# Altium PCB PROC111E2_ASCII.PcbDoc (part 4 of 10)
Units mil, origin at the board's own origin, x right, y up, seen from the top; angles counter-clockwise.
Board outline 7700 x 2300 mil, 6 copper layers (Top Layer, GND 1, SIG 1, SIG 2, GND 2, Bottom Layer), stack 78.711 mil thick; 767 components, 596 nets, 2755 pads, 1578 vias.
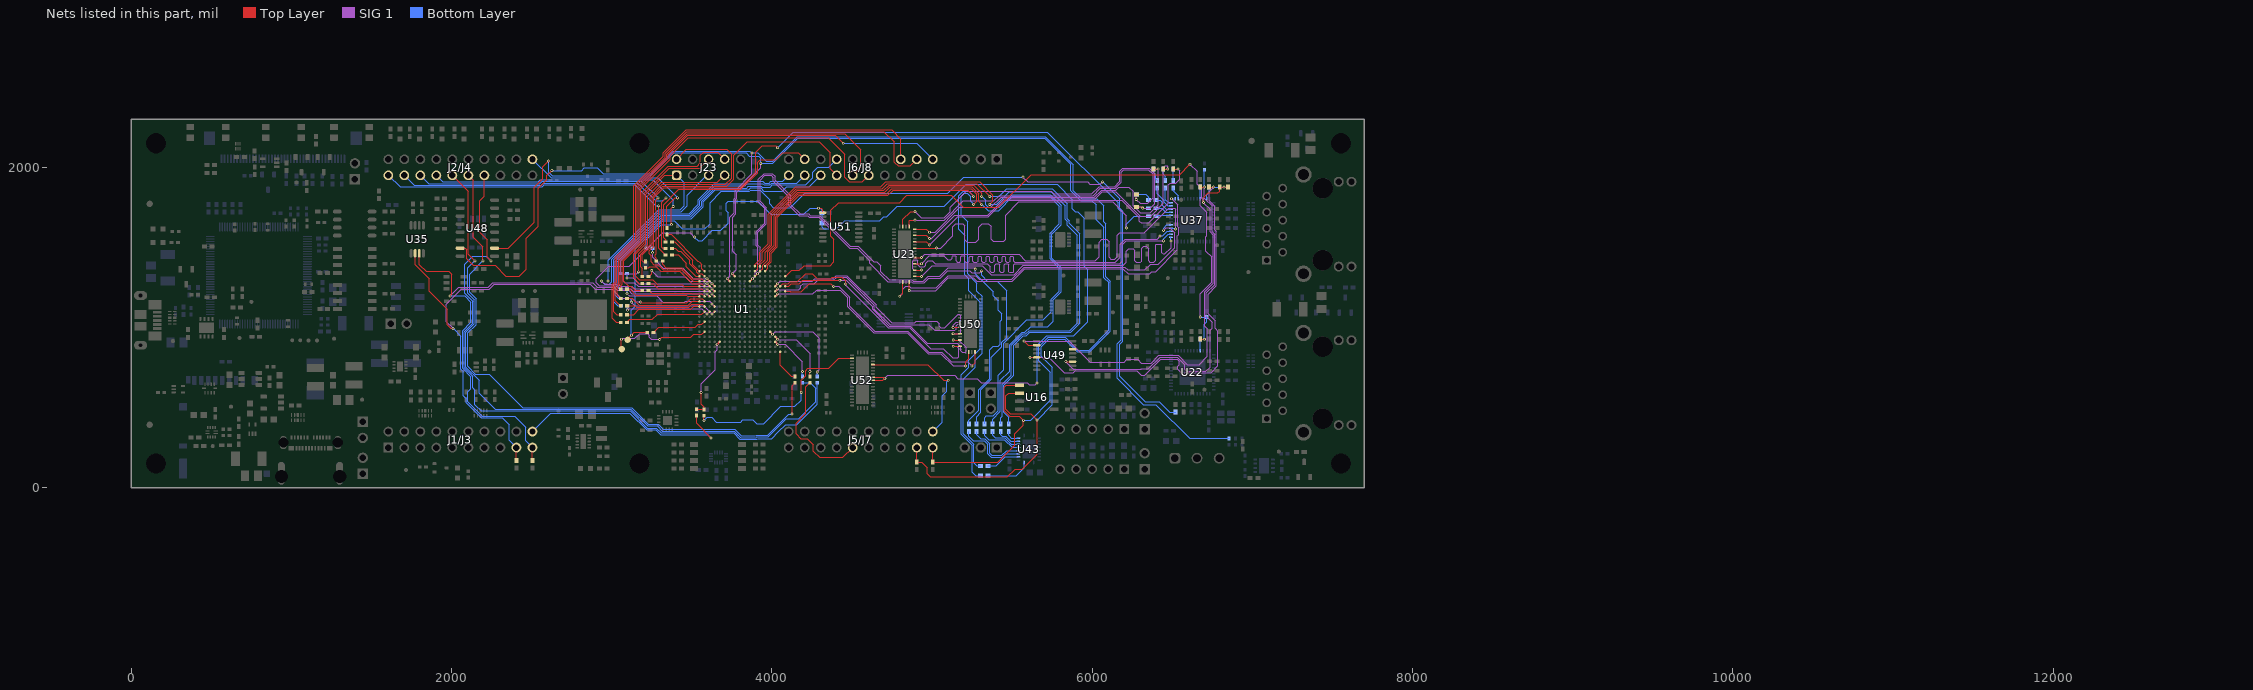
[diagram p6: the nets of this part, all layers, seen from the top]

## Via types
v1: diameter 18, hole 8, Top Layer to Bottom Layer, tented both sides, 1474 vias
v2: diameter 19.68, hole 7.87, Top Layer to Bottom Layer, tented both sides, 104 vias

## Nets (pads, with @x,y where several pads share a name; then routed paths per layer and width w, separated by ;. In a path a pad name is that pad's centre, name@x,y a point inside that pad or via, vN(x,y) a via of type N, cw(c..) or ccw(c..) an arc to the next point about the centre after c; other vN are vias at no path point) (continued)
AM263_BP_MUX_SEL_GPIO63: R298.2 R300.2 U1.G4 U51.1 U52.9 U52.10 | length 7040.3
  Top Layer w5.3: v1(4291.03,1744.24) 4306.84,1744.24 4317.8,1733.28 U51.1@4317.8,1717.48 ; U52.9@4629.96,670 4693.01,670 v1(4705,681.99) 4697.31,689.68 U52.10@4629.96,689.68
  Top Layer w10: v1(3625.87,1209.57) U1.G4@3641.62,1193.82
  SIG 1 w4: 3518.68,1226.06 3609.38,1226.06 v1(3625.87,1209.57)
  SIG 1 w4.75: v1(3515.64,1564.46) 3488.69,1591.41 3317.97,1591.41 3109.37,1382.8 2979.62,1382.8 2902.31,1305.49 2902.31,1278.83 2921.14,1260 3024.5,1260 3042.5,1242 3116.39,1242 3132.32,1226.06 3518.68,1226.06
  SIG 1 w5.3: v1(4705,681.99) 4723.17,700.16 5141.38,700.16 5161.5,680.04 5281.04,680.04 5305.58,655.5 5592.71,655.5 5605.21,643 5644.31,643 v1(5654.39,653.09)
  Bottom Layer w5.3: v1(3515.64,1564.46) 3538.74,1541.35 3563.03,1541.35 3627.8,1606.12 3680.51,1606.12 3726.52,1652.14 3726.52,1715.86 3713.62,1728.77 3713.62,1775.16 3725.58,1787.12 3911.05,1787.12 3991.69,1706.48 4199.68,1706.48 4237.44,1744.24 v1(4291.03,1744.24) 4301.08,1744.24 4312.89,1732.43 R298.2@4312.89,1715.49 R300.2@4312.89,1652.52 4312.89,1626.91 4323,1616.79 4405.75,1616.79 4453.96,1665 4672.04,1665 4697.54,1690.5 4717.5,1690.5 4783.54,1756.54 5075.54,1756.54 5212,1893 5782.5,1893 5876.5,1799 5876.5,1741.5 5894,1724 5908.74,1724 5951,1681.74 5951,1383.57 5972.85,1361.72 5972.85,1035.35 5885.7,948.2 5714.61,948.2 5655,888.59 5655,653.69 v1(5654.39,653.09)
AM263_CAN_STB_GPIO51: R248.2 U1.D1 | length 6072.1
  Top Layer w4: 3515.64,1288.31 U1.D1@3547.13,1288.31
  Top Layer w5.3: 3515.64,1288.31 3507.89,1288.31 3435.14,1361.06 3322.44,1361.06 3291,1392.5 3263,1392.5 3246.28,1409.22 3246.28,1447.41 3234.85,1458.85 3234.85,1478.14 3261.6,1504.89 3261.6,1810.22 3323.68,1872.3 3801.74,1872.3 3899.52,1970.08 3899.52,2094.24 3940.28,2135 4022.68,2135 v1(4035.32,2122.36)
  Bottom Layer w5.3: v1(4035.32,2122.36) 4132.97,2220 5720,2220 6161.25,1778.75 6161.25,1740.07 6179.88,1721.45 6179.88,922.38 6155,897.5 6155,683.66 6320,518.66 6397.07,518.66 6608.49,307.24 R248.2@6855,307.24
AM263_CLKOUT0: R4.2 R118.1 TP1.1 | length 5760.5
  Top Layer w5.3: TP1.1@3098.87,922.75 3098.87,928.07 v1(3122.32,951.52) 3139.85,969.06 R4.2@3221.22,969.06
  SIG 1 w4.75: v1(5567.49,1938.61) 5596.85,1909.25 5970.75,1909.25 5984.25,1895.75 6051.33,1895.75 v1(6065,1909.42)
  Bottom Layer w5.3: v1(3122.32,951.52) 3122.32,1108.82 3144.52,1131.02 3144.52,1491.6 3317.93,1665 3389.12,1665 3439.12,1615 3580,1615 3613.9,1648.9 3613.9,1778.89 3684.53,1849.52 3858.86,1849.52 3867.31,1857.97 3925.21,1857.97 3985,1798.18 3985,1773.13 4009.25,1748.88 4114.83,1748.88 4204.88,1838.92 5097.92,1838.92 5197.61,1938.61 v1(5567.49,1938.61) ; v1(6065,1909.42) 6171.85,1802.57 6171.85,1744.46 6190.48,1725.84 6190.48,912.98 6171.85,894.35 6171.85,695.04 6330,536.89 6417.03,536.89 6482.54,471.38 R118.1@6520,471.38
AM263_CLKOUT0_R: R4.1 U1.M2 | length 345.9
  Top Layer w4: 3539.45,1020.59 3562.88,1020.59 U1.M2@3578.63,1036.34
  Top Layer w5.3: R4.1@3260.59,969.06 3293.06,1001.54 3520.39,1001.54 3539.45,1020.59
AM263_DAC_OUT1: J1/J3.30 R45.1 | length 1403.7
  Top Layer w5.3: R45.1@3528.72,450.24 3528.72,400.34 v1(3618.83,310.23)
  Bottom Layer w5.3: J1/J3.30@2504.17,350 2619.17,465 3112.73,465 3216.45,361.28 3273.73,361.28 3304.51,330.5 3598.56,330.5 v1(3618.83,310.23)
AM263_DAC_OUT2: R3.1 U52.23 | length 1253.4
  Top Layer w5.3: v1(3575.19,418.7) R3.1@3575.19,448.84 ; v1(4182.78,594.53) 4181.82,595.49 4181.82,670.64 4209.52,698.35 4209.52,729.88 4223.55,743.91 4353.02,743.91 4416.91,807.8 U52.23@4500.04,807.8
  Bottom Layer w5.3: v1(3575.19,418.7) 3594.71,438.22 3622.55,438.22 3651.67,409.1 3803.38,409.1 3818.8,424.52 3880.9,424.52 3905.95,399.46 3948.02,399.46 4054.9,506.35 4142.26,506.35 4182.08,546.17 4182.08,593.83 v1(4182.78,594.53)
AM263_DAC_OUT2_SDFM0_CLK3: J5/J7.70 U52.14 | length 871.6
  Top Layer w5.3: U52.14@4629.96,768.43 4973.69,768.43 5071.52,670.59 v1(5100.56,670.59)
  Bottom Layer w5.3: J5/J7.70@5004.17,350 5063.33,409.15 5063.33,573.33 5092.52,602.52 5092.52,661.13 5100.56,669.16 v1(5100.56,670.59)
AM263_DAC_OUT_R: R3.2 R45.2 U1.T5 | length 523.2
  Top Layer w5.3: R45.2@3528.72,489.61 3573.8,489.61 R3.2@3574.55,488.85 ; v1(3557.81,594.15) 3557.81,521.62 3574.55,504.87 R3.2@3574.55,488.85 ; R3.2@3575.19,488.21 R3.2@3574.55,488.85
  Top Layer w10: v1(3657.37,894.61) U1.T5@3673.12,910.35
  SIG 1 w4: 3645,815.87 3645,848.34 3657.37,860.71 v1(3657.37,894.61)
  SIG 1 w4.75: v1(3557.81,594.15) 3557.81,649.18 3645,736.37 3645,815.87
AM263_EPWM0_A: J2/J4.11 R46.1 | length 1229.8
  Top Layer w5.3: R46.1@3344.16,1620.17 3344.16,1756.66 3396.77,1809.27 v1(3410.06,1809.27)
  Bottom Layer w5.3: J2/J4.11@2504.17,2050 2620.48,1933.69 3285.64,1933.69 v1(3410.06,1809.27)
AM263_EPWM0_A_R: R46.2 U1.B2 | length 343.2
  Top Layer w4: 3536.77,1414.29 3537.52,1413.54 3539.53,1413.54 3547.44,1405.64 3547.58,1405.64 3562.88,1390.34 3562.88,1367.05 U1.B2@3578.63,1351.3
  Top Layer w5.3: R46.2@3344.16,1580.8 3370.27,1580.8 3536.77,1414.29
AM263_EPWM0_B: J6/J8.59 R47.1 | length 1309.3
  Top Layer w5.3: R47.1@3335.32,1534 3335.32,1548.68 3323,1561 3323,1766.4 3418.3,1861.7 3806.13,1861.7 3910.48,1966.05 3910.48,2032.84 3926.33,2048.69 4024.01,2048.69 4066.36,2091.04 4163.14,2091.04 J6/J8.59@4204.17,2050
AM263_EPWM0_B_R: R47.2 U1.B1 | length 264.5
  Top Layer w4: 3515.64,1382.8 U1.B1@3547.13,1351.3
  Top Layer w5.3: R47.2@3374.69,1534 3392.43,1534 3506.5,1419.93 3506.5,1391.93 3515.64,1382.8
AM263_EPWM1_A: J2/J4.37 R48.1 | length 1962.1
  Top Layer w5.3: v1(3372,1642) 3372,1744.5 v1(3383,1755.5)
  Bottom Layer w5.3: J2/J4.37@1904.17,1950 1945.21,1908.96 2540,1908.96 2554.13,1923.09 3253.91,1923.09 3383,1794 v1(3383,1755.5) v1@3383,1753.5 ; R48.1@3215,1495 3215,1547.08 3309.92,1642 v1(3372,1642)
AM263_EPWM1_A_R: R48.2 U1.D3 | length 475.4
  Top Layer w10: v1(3594.38,1304.06) U1.D3@3610.12,1288.31
  SIG 1 w4: 3515.64,1304.06 v1(3594.38,1304.06)
  SIG 1 w4.75: v1(3254.37,1466.94) 3254.37,1436.87 3321.24,1370 3442.05,1370 3507.99,1304.06 3515.64,1304.06
  Bottom Layer w5.3: v1(3254.37,1466.94) R48.2@3254.37,1495
AM263_EPWM1_B: J2/J4.38 R49.1 | length 1962.2
  Top Layer w5.3: R49.1@3277.82,1415.5 3277.82,1431.37 3271.87,1437.32 3271.87,1453 3278.62,1459.75 3278.62,1725.38 3272.69,1731.31 3272.69,1793.93 3288.03,1809.27 v1(3288.27,1809.27)
  Bottom Layer w5.3: J2/J4.38@1804.17,1950 1855.81,1898.36 2550,1898.36 2564.13,1912.49 3185.05,1912.49 v1(3288.27,1809.27)
AM263_EPWM1_B_R: R49.2 U1.D2 | length 327
  Top Layer w4: 3515.64,1305.38 3561.56,1305.38 U1.D2@3578.63,1288.31
  Top Layer w5.3: R49.2@3317.19,1415.5 3317.19,1393.51 3336.94,1373.76 3437.43,1373.76 3505.81,1305.38 3515.64,1305.38
AM263_EPWM2_A: J2/J4.39 R50.1 | length 2066.5
  Top Layer w5.3: R50.1@3335.32,1493.5 3318.5,1493.5 3311.86,1500.14 3311.86,1782.87 v1(3338.27,1809.27)
  Bottom Layer w5.3: J2/J4.39@1704.17,1950 1766.41,1887.76 2560,1887.76 2574.13,1901.89 3160.45,1901.89 3272.6,1789.75 3318.74,1789.75 v1(3338.27,1809.27)
AM263_EPWM2_A_R: R50.2 U1.C2 | length 293.2
  Top Layer w4: 3529.96,1345.78 3540.19,1335.55 3562.88,1335.55 U1.C2@3578.63,1319.8
  Top Layer w5.3: R50.2@3374.69,1493.5 3396.05,1493.5 3413.55,1476 3429.32,1476 3486.25,1419.07 3486.25,1396.25 3529.96,1352.54 3529.96,1345.78
AM263_EPWM2_B: J2/J4.40 R51.1 | length 2099.5
  Top Layer w5.3: v1(3292.21,1759.27) 3292.21,1494.79 3333.5,1453.5 R51.1@3335.32,1453.5
  Bottom Layer w5.3: J2/J4.40@1604.17,1950 1677.01,1877.16 2564.39,1877.16 2578.52,1891.29 3142.38,1891.29 3274.4,1759.27 v1@3288.27,1759.27
AM263_EPWM2_B_R: R51.2 U1.C1 | length 241.8
  Top Layer w5.3: R51.2@3374.69,1453.5 3414.01,1453.5 3465.77,1401.75 3465.77,1377.91 3523.87,1319.8 U1.C1@3547.13,1319.8
AM263_EPWM3_A: J6/J8.77 R52.1 | length 1974
  Top Layer w5.3: R52.1@3210.5,1411.61 3195.56,1411.61 3190.98,1416.19 3190.98,1452.49 3251,1512.51 3251,1814.61 3319.29,1882.9 3717.56,1882.9 3761.17,1926.51 3761.17,2075 3846.17,2160 4295,2160 4363.14,2091.86 4363.14,1991.04 J6/J8.77@4404.17,1950
AM263_EPWM3_A_R: R52.2 U1.E2 | length 420.3
  Top Layer w4: 3515.64,1272.56 3562.88,1272.56 U1.E2@3578.63,1256.81
  Top Layer w5.3: R52.2@3210.5,1372.24 3230.24,1372.24 3235.5,1377.5 3276,1377.5 3304,1349.5 3425.03,1349.5 3501.97,1272.56 3515.64,1272.56
AM263_EPWM3_B: J6/J8.78 R53.1 | length 1578.6
  Bottom Layer w5.3: R53.1@3055.32,1341.34 3055.32,1417.38 3317.69,1679.75 3495.49,1679.75 3570.48,1754.74 3570.48,1783.55 3647.05,1860.12 3854.47,1860.12 3865.8,1871.46 3929.38,1871.46 3948.98,1851.85 4064.19,1851.85 4092.34,1880 4234.17,1880 J6/J8.78@4304.17,1950
AM263_EPWM3_B_R: R53.2 U1.E3 | length 564.1
  Top Layer w10: v1(3594.38,1272.56) U1.E3@3610.12,1256.81
  SIG 1 w4: 3515.64,1272.56 v1(3594.38,1272.56)
  SIG 1 w4.75: v1(3094.69,1309.45) 3132.55,1309.45 3169.44,1272.56 3515.64,1272.56
  Bottom Layer w5.3: v1(3094.69,1309.45) R53.2@3094.69,1336.34
AM263_EPWM9_A: J6/J8.75 R9.1 | length 2465.8
  Top Layer w5.3: R9.1@3055.09,1238.11 3055.09,1259.45 3064.56,1268.92 3064.56,1420.53 3180.1,1536.07 3180.1,1867.1 3363.9,2050.9 3363.9,2073.4 3475.85,2185.35 4351.06,2185.35 4455.62,2080.8 4455.62,1936.68 4483.33,1908.96 4563.14,1908.96 J6/J8.75@4604.17,1950
AM263_EPWM9_A_R: R9.2 U1.G1 | length 471
  Top Layer w4: 3515.64,1193.82 U1.G1@3547.13,1193.82
  Top Layer w5.3: R9.2@3094.46,1238.11 3113.89,1238.11 3149.38,1202.62 3465.6,1202.62 3474.41,1193.82 3515.64,1193.82
AM263_EPWM9_B: J6/J8.76 R12.1 | length 2579.5
  Top Layer w5.3: R12.1@3055.09,1135.05 3053.12,1135.05 3022.15,1166.01 3022.15,1256.7 3042.4,1276.95 3042.4,1428.35 3158.9,1544.85 3158.9,1875.88 3342.7,2059.68 3342.7,2082.18 3469.91,2209.39 4453.93,2209.39 4460.46,2202.85 4463.32,2200 4553.32,2110 4553.32,1999.15 J6/J8.76@4504.17,1950
AM263_EPWM9_B_R: R12.2 U1.J2 | length 501.2
  Top Layer w4: 3515.64,1145 3564.46,1145 U1.J2@3578.63,1130.83
  Top Layer w5.3: R12.2@3094.46,1135.05 3144.95,1135.05 3153.47,1126.53 3481.53,1126.53 3500,1145 3515.64,1145
AM263_EPWM11_A: J6/J8.51 R13.1 | length 2801.9
  Top Layer w5.3: R13.1@3055.09,1181.64 3053.12,1181.64 3032.75,1202.01 3032.75,1252.31 3053,1272.56 3053,1423.96 3169.5,1540.46 3169.5,1871.49 3353.3,2055.29 3353.3,2077.79 3474.3,2198.79 4396.21,2198.79 v1(4445,2150)
  Bottom Layer w5.3: v1(4445,2150) 4904.17,2150 J6/J8.51@5004.17,2050
AM263_EPWM11_A_R: R13.2 U1.H1 | length 481.5
  Top Layer w4: 3515.64,1162.32 U1.H1@3547.13,1162.32
  Top Layer w5.3: R13.2@3094.46,1181.64 3125.36,1181.64 3169.87,1137.13 3477.14,1137.13 3502.33,1162.32 3515.64,1162.32
AM263_EPWM11_B: J6/J8.52 R99.1 | length 2978.9
  Top Layer w5.3: R99.1@3053.12,1079.62 3030.38,1079.62 3011.55,1098.45 3011.55,1261.09 3031.8,1281.34 3031.8,1432.74 3148.3,1549.24 3148.3,1880.27 3332.1,2064.07 3332.1,2086.57 3468.62,2223.09 4698.52,2223.09 4763.14,2158.47 4763.14,2033 4787.17,2008.96 4864.48,2008.96 4904.17,2048.66 J6/J8.52@4904.17,2050
AM263_EPWM11_B_R: R99.2 U1.J1 | length 473.9
  Top Layer w4: 3515.64,1130.83 U1.J1@3547.13,1130.83
  Top Layer w5.3: R99.2@3094.46,1079.62 3135.36,1079.62 3167.91,1112.16 3491.53,1112.16 3510.19,1130.83 3515.64,1130.83
AM263_EPWM12_A: J6/J8.53 R280.1 | length 2922.6
  Top Layer w5.3: R280.1@3055.09,1031.94 3027.09,1031.94 3000.95,1058.08 3000.95,1265.48 3021.2,1285.73 3021.2,1437.13 3137.7,1553.63 3137.7,1884.66 3321.5,2068.46 3321.5,2090.96 3464.22,2233.69 4747.04,2233.69 4804.17,2176.55 J6/J8.53@4804.17,2050
AM263_EPWM12_A_R: R280.2 U1.K2 | length 512.1
  Top Layer w4: 3515.64,1083.58 3562.88,1083.58 U1.K2@3578.63,1099.33
  Top Layer w5.3: R280.2@3094.46,1031.94 3112.52,1050 3252.62,1050 3286.2,1083.58 3515.64,1083.58
AM263_EPWM12_B: J6/J8.57 R281.1 | length 1858.4
  Bottom Layer w5.3: R281.1@3055.32,1239.6 3032.98,1261.93 3032.98,1410.04 3313.3,1690.35 3491.1,1690.35 3559.88,1759.13 3559.88,1787.94 3642.66,1870.72 3841.76,1870.72 3853.09,1882.06 3933.77,1882.06 3939.13,1876.69 3987.7,1876.69 4001.91,1890.9 4211.79,1890.9 4254.82,1933.93 4254.82,1970 4284.82,2000 4354.17,2000 J6/J8.57@4404.17,2050
AM263_EPWM12_B_R: R281.2 U1.J4 | length 612.5
  Top Layer w10: v1(3625.87,1146.57) U1.J4@3641.62,1130.83
  SIG 1 w4: 3515.64,1162.63 3609.82,1162.63 v1(3625.87,1146.57)
  SIG 1 w4.75: v1(3094.46,1211) 3108.26,1197.2 3279.76,1197.2 3318.53,1158.44 3453.95,1158.44 3458.15,1162.63 3515.64,1162.63
  Bottom Layer w5.3: v1(3094.46,1211) 3094.69,1211.23 R281.2@3094.69,1239.6
AM263_EPWM13_A: J6/J8.79 R59.1 | length 1681.2
  Bottom Layer w5.3: R59.1@3055.32,1181.51 3040.47,1181.51 3022.38,1199.6 3022.38,1414.43 3308.91,1700.95 3486.71,1700.95 3549.28,1763.52 3549.28,1792.33 3642.74,1885.8 3832,1885.8 3842.6,1896.4 3943.72,1896.4 3950.24,1889.88 3985.9,1889.88 3997.52,1901.5 4155.67,1901.5 J6/J8.79@4204.17,1950
AM263_EPWM13_A_R: R59.2 U1.K4 | length 602
  Top Layer w10: v1(3625.87,1083.58) U1.K4@3641.62,1099.33
  SIG 1 w4.75: v1(3121.5,1157.83) 3144.33,1135 3574.46,1135 v1(3625.87,1083.58)
  Bottom Layer w5.3: R59.2@3094.69,1181.51 3111.49,1181.51 3121.5,1171.5 v1(3121.5,1157.83)
AM263_EPWM13_B: J6/J8.80 R60.1 | length 1655.1
  Bottom Layer w5.3: R60.1@3056.12,1135.05 3036.98,1135.05 3011.78,1160.25 3011.78,1423.57 3299.76,1711.55 3482.32,1711.55 3538.68,1767.91 3538.68,1796.72 3638.35,1896.4 3827.61,1896.4 3843.32,1912.1 3943.01,1912.1 3954.63,1900.48 3981.51,1900.48 3993.13,1912.1 4066.27,1912.1 J6/J8.80@4104.17,1950
AM263_EPWM13_B_R: R60.2 U1.K3 | length 564.1
  Top Layer w10: v1(3594.38,1083.58) U1.K3@3610.12,1099.33
  SIG 1 w4.75: v1(3097.46,1108.15) 3106.94,1117.63 3560.33,1117.63 v1(3594.38,1083.58)
  Bottom Layer w5.3: v1(3097.46,1108.15) R60.2@3097.46,1135.05
AM263_EPWM14_A: J2/J4.35 R282.1 | length 3769.6
  Top Layer w5.3: J2/J4.35@2104.17,1950 2135.38,1918.8 2135.38,1563.41 2195,1503.78 v1(2195,1415.64) ; v1(4125,458.99) 4125,637 R282.1@4143,655
  Bottom Layer w5.3: v1(2195,1415.64) 2111.44,1332.08 2111.44,1221.08 2152,1180.52 2152,1018.21 2099.19,965.4 2099.19,757.06 2147.28,708.97 2235.3,708.97 2444.41,499.86 3122.84,499.86 3227.09,395.61 3288.59,395.61 3321.3,362.9 3768.39,362.9 3808.74,322.55 3896.73,322.55 3901.79,327.6 3972.6,327.6 4103.99,458.99 v1(4125,458.99)
AM263_EPWM14_A_R: R282.2 U1.V17 | length 204.1
  Top Layer w5.3: U1.V17@4051.07,847.36 4051.07,763.99 4120.69,694.37 R282.2@4143,694.37
AM263_EPWM14_B: J2/J4.36 R283.1 | length 4000.5
  Top Layer w5.3: J2/J4.36@2004.17,1950 2104.17,1850 2104.17,1456.47 v1(2145,1415.64)
  Bottom Layer w5.3: v1(2145,1415.64) 2100.84,1371.48 2100.84,1214.16 2141.4,1173.6 2141.4,1022.6 2088.59,969.79 2088.59,752.67 2171.32,669.93 2171.32,589.92 2271.98,489.26 3118.45,489.26 3222.71,385 3283.51,385 3316.21,352.3 3763.99,352.3 3804.35,311.95 3901.12,311.95 3906.18,317 3976.99,317 4090,430 4167.53,430 4272.54,535.02 4272.54,620.15 4237.69,655 R283.1@4190,655
AM263_EPWM14_B_R: R283.2 U1.T16 | length 313.8
  Top Layer w10: U1.T16@4019.57,910.35 v1(4035.32,894.61)
  SIG 1 w4.75: v1(4035.32,894.61) 4081.83,894.61 4190,786.43 v1(4190,724.36)
  Bottom Layer w5.3: R283.2@4190,694.37 v1(4190,724.36)
AM263_EPWM15_A: J2/J4.34 R284.1 | length 4169.5
  Top Layer w5.3: J2/J4.34@2204.17,1950 2204.17,1819.87 2175,1790.7 2175,1593.86 2220.89,1547.97 2220.89,1439.75 v1(2245,1415.64)
  Bottom Layer w5.3: v1(2245,1415.64) 2217.11,1443.54 2131.42,1443.54 2081.83,1393.95 2081.83,1213.17 2130.8,1164.2 2130.8,1026.99 2077.99,974.18 2077.99,748.28 2130.48,695.79 2130.48,622.41 2145,607.89 2145,517.39 2183.73,478.66 3114.06,478.66 3220.85,371.88 3278.12,371.88 3308.3,341.7 3759.6,341.7 3799.96,301.35 3905.52,301.35 3910.57,306.4 3998.57,306.4 4042.93,350.77 4084.9,392.74 4154.2,392.74 4283.14,521.68 4283.14,654.64 R284.1@4282.78,655
AM263_EPWM15_A_R: R284.2 U1.P15 | length 580
  Top Layer w10: U1.P15@3988.08,973.35 v1(4003.83,957.6)
  SIG 1 w4: v1(4003.83,957.6) 4018.83,972.6 4041.54,972.6
  SIG 1 w4.75: 4041.8,972.86 4255.88,972.86 4295,933.74 4295,734.48 v1(4282.93,722.41)
  Bottom Layer w5.3: R284.2@4282.93,694.37 v1(4282.93,722.41)
AM263_EPWM15_B: J5/J7.45 R285.1 | length 818.3
  Top Layer w5.3: R285.1@4236.47,655 4210.42,628.95 4210.42,462.84 4150,402.43 4150,335 4180,305 4219.59,305 4258.64,265.95 4258.64,227.31 4296.85,189.1 4443.27,189.1 J5/J7.45@4504.17,250
AM263_EPWM15_B_R: R285.2 U1.R16 | length 404.4
  Top Layer w5.3: R285.2@4236.47,696.32 v1(4236.47,724.38)
  Top Layer w10: U1.R16@4019.57,941.85 v1(4035.32,926.1)
  SIG 1 w4.75: v1(4035.32,926.1) 4037.75,923.67 4151.15,923.67 4239.59,835.24 4239.59,733.79 4239,733.2 4239,726.92 v1(4236.47,724.38)
AM263_EQEP0_A: R328.1 U1.B14 | length 3715.4
  Top Layer w5.3: U1.B14@3956.58,1351.3 3973.55,1368.27 3973.55,1388.81 3995.2,1410.46 3995.2,1464.6 4033.75,1503.15 4033.75,1688.08 4169.83,1824.16 4724.16,1824.16 4755.96,1855.96 5222.2,1855.96 v1(5259.51,1818.66)
  Bottom Layer w5.3: v1(5259.51,1818.66) 5228.17,1850 5195,1850 5167.5,1822.5 5167.5,1612 5204.25,1575.25 5204.25,1328.63 5228.38,1304.5 5228.38,1230 5301.68,1156.71 5301.68,867.97 5228.7,795 5228.7,750 5182.22,703.52 5182.22,332.77 5250,264.99 5250,96.38 5271.38,75 R328.1@5301.38,75
AM263_EQEP0_A_R: R328.2 U43.1 | length 277.2
  Bottom Layer w5.3: R328.2@5348.62,75 5524.13,75 5574.13,125 U43.1@5574.13,155.98
AM263_EQEP0_B: R329.1 U1.A14 | length 3726.7
  Top Layer w5.3: U1.A14@3956.58,1382.8 3956.58,1384.99 3984.6,1413.01 3984.6,1468.99 4023.15,1507.54 4023.15,1692.47 4165.44,1834.76 4716.52,1834.76 4748.32,1866.56 5243.44,1866.56 5279.38,1830.62 5279.38,1788.54 v1(5259.51,1768.66)
  Bottom Layer w5.3: v1(5259.51,1768.66) 5239.98,1788.18 5239.98,1816.52 5218.32,1838.18 5201.42,1838.18 5181.5,1818.26 5181.5,1699.88 5222.5,1658.88 5222.5,1334.24 5279.52,1277.22 5279.52,1226.22 5312.28,1193.47 5312.28,838.75 5268.53,795 5268.53,752.23 5192.82,676.53 5192.82,337.16 5260.6,269.38 5260.6,266.68 5261.17,266.11 5261.17,153.83 5279.91,135.09 R329.1@5301.38,135.09
AM263_EQEP0_B_R: R329.2 U43.3 | length 213.4
  Bottom Layer w5.3: R329.2@5348.62,135.09 5399.09,135.09 5455.41,191.41 U43.3@5538.7,191.41
AM263_EQEP0_INDEX: R330.1 U1.D11 | length 3586.3
  Top Layer w10: U1.D11@3862.09,1288.31 v1(3877.84,1304.06)
  SIG 1 w4: v1(3877.84,1304.06) 3894.34,1320.55 3894.34,1343.12 3910.09,1358.87 3910.09,1414.29
  SIG 1 w4.75: 3910.09,1414.29 3910.09,1501.49 3901.4,1510.18 3901.4,1598.41 3953.46,1650.48 3953.46,1744.32 3915.15,1782.62 3915.15,1923.92 3950.58,1959.35 4002.94,1959.35 4018.98,1943.31 4018.98,1918.05 4116.01,1821.01 4116.01,1767.44 4174.9,1708.55 4228.8,1708.55 4239.67,1697.68 4296.89,1697.68 4487.65,1506.92 4538.36,1506.92 4635.28,1410 4654.74,1410 4679.81,1384.94 4679.81,1347.98 4730.92,1296.87 4874.31,1296.87 4881.78,1289.4 4945.95,1289.4 4975.26,1318.71 5047.28,1318.71 5100.07,1371.5 5262.15,1371.5 v1(5269.65,1364)
  Bottom Layer w5.3: R330.1@5229.44,397.13 5229.44,421.97 5289.73,482.26 5289.73,611.02 5359.88,681.17 5359.88,860.04 5382.23,882.4 5412.4,882.4 5424.59,894.59 5424.59,1037.74 5435,1048.15 5435,1084.57 5413.5,1106.07 5413.5,1165.36 5382.23,1196.63 5382.23,1222.76 5269.65,1335.35 v1(5269.65,1364)
AM263_EQEP0_INDEX_R: R330.2 U43.4 | length 435.2
  Bottom Layer w5.3: R330.2@5229.44,349.89 5229.44,320.8 5257.23,293 5324.19,293 5347.18,270.02 5347.18,212.16 5369.34,190 5439.01,190 5460.1,211.1 U43.4@5538.7,211.1
AM263_EQEP0_STROBE: R331.1 U1.C12 | length 3559.5
  Top Layer w10: U1.C12@3893.59,1319.8 v1(3909.34,1335.55)
  SIG 1 w4: v1(3909.34,1335.55) 3925.83,1352.05 3925.83,1414.29
  SIG 1 w4.75: 3925.83,1414.29 3925.83,1499.95 3911.45,1514.34 3911.45,1594.25 3963.51,1646.32 3963.51,1748.48 3925.2,1786.79 3925.2,1919.76 3954.74,1949.3 3993.83,1949.3 4008.93,1934.21 4008.93,1913.89 4105.96,1816.85 4105.96,1763.28 4170.74,1698.5 4222.99,1698.5 4233.86,1687.63 4292.73,1687.63 4484.49,1495.87 4531.12,1495.87 4610.15,1416.84 4610.15,1399.73 4723.06,1286.82 4870.15,1286.82 4877.61,1279.35 4950.12,1279.35 4979.43,1308.66 5051.44,1308.66 5097.78,1355 5236.5,1355 5249,1342.5 5298.5,1342.5 v1(5309.5,1353.5)
  Bottom Layer w5.3: R331.1@5277.45,397.13 5277.45,442.72 5304.1,469.37 5304.1,610.4 5370.48,676.78 5370.48,815.42 5435.19,880.14 5435.19,906.89 5465.38,937.08 5465.38,1229.97 5405.35,1290 5344.5,1290 5309.5,1325 v1(5309.5,1353.5)
AM263_EQEP0_STROBE_R: R331.2 U43.5 | length 382
  Bottom Layer w5.3: R331.2@5277.45,349.89 5277.45,331.1 5303.54,305 5330,305 5361.17,273.83 5361.17,213.16 5373.5,200.83 5434.84,200.83 5464.8,230.78 U43.5@5538.7,230.78
AM263_EQEP2_A: R332.1 U1.B13 | length 4078.1
  Top Layer w4: U1.B13@3925.09,1351.3 3940.83,1367.05 3940.83,1387.93
  Top Layer w5.3: 3940.83,1387.93 3972.4,1419.5 3972.4,1471.79 4012.55,1511.93 4012.55,1696.86 4161.05,1845.36 4705.36,1845.36 4737.16,1877.16 5247.84,1877.16 5289.98,1835.02 5289.98,1788.18 v1(5309.51,1768.66)
  Bottom Layer w5.3: v1(5309.51,1768.66) 5310.4,1768.66 5349.66,1729.4 5415.42,1729.4 5504.22,1818.2 5734.35,1818.2 5794.52,1758.03 5794.52,1646.1 5736.23,1587.8 5736.23,1427.78 5794.52,1369.49 5794.52,1226.91 5787.86,1220.25 5787.86,1219.97 5744.4,1176.5 5744.4,1097.83 5694.68,1048.11 5591.4,1048.11 5445.79,902.5 5445.79,735.68 5413.06,702.96 5413.06,478.39 5382.77,448.1 5338.15,448.1 5327.45,437.4 R332.1@5327.45,397.13
AM263_EQEP2_A_R: R332.2 U43.6 | length 266.9
  Bottom Layer w5.3: R332.2@5327.45,349.89 5327.45,325.16 5352.6,300 5449.54,300 5499.07,250.47 U43.6@5538.7,250.47
AM263_EQEP2_B: R333.1 U1.A13 | length 4039
  Top Layer w4: U1.A13@3925.09,1382.8 3925.09,1392.08
  Top Layer w5.3: 3925.09,1392.08 3956.58,1423.58 3956.58,1470.96 3999.4,1513.78 3999.4,1698.71 4156.66,1855.96 4699.21,1855.96 4731.01,1887.76 5258.54,1887.76 5309.51,1836.79 v1(5309.51,1818.66)
  Bottom Layer w5.3: v1(5309.51,1818.66) 5335,1793.17 5335,1765.56 5351.42,1749.14 5420.16,1749.14 5499.83,1828.8 5738.74,1828.8 5805.12,1762.42 5805.12,1641.71 5746.83,1583.41 5746.83,1432.17 5805.12,1373.88 5805.12,1222.24 5755,1172.11 5755,1038.76 5721.24,1005 5614.98,1005 5579.67,969.69 5561.6,969.69 5484.84,892.93 5484.84,727.99 5426.85,670 5426.85,475.45 5377.45,426.05 R333.1@5377.45,397.13
AM263_EQEP2_B_R: R333.2 U43.7 | length 207.4
  Bottom Layer w5.3: R333.2@5377.45,349.89 5377.45,327.55 5394.4,310.6 5453.93,310.6 5494.38,270.15 U43.7@5538.7,270.15
AM263_EQEP2_INDEX: R334.1 U1.A12 | length 4237.5
  Top Layer w5.3: U1.A12@3893.59,1382.8 3893.59,1391.19 3923.85,1421.45 3923.85,1468.2 3977.48,1521.84 3977.48,1706.77 4147.88,1877.16 4679.53,1877.16 4711.33,1908.96 5296.81,1908.96 5379.48,1826.3 5379.48,1788.63 v1(5359.51,1768.66)
  Bottom Layer w5.3: v1(5359.51,1768.66) 5402.86,1768.66 5481.51,1847.31 5742.69,1847.31 5830,1760 5830,1676.8 5844.52,1662.28 5844.52,1637.83 5907.5,1574.85 5907.5,1027.26 5860.24,980 5604.97,980 5584.06,959.09 5565.99,959.09 5495.44,888.54 5495.44,702.96 5437.45,644.97 5437.45,446.35 5428.06,436.97 R334.1@5428.06,397.13
AM263_EQEP2_INDEX_R: R334.2 U43.8 | length 147.2
  Bottom Layer w5.3: R334.2@5428.06,349.89 5428.06,330 5436.86,321.2 5458.32,321.2 5489.68,289.84 U43.8@5538.7,289.84
AM263_EQEP2_STROBE: R335.1 U1.B12 | length 4192.9
  Top Layer w4: U1.B12@3893.59,1351.3 3910,1367.71 3910,1385
  Top Layer w5.3: 3910,1385 3910,1391.99 3940,1421.99 3940,1469.37 3988.08,1517.45 3988.08,1702.38 4152.27,1866.56 4687.63,1866.56 4719.43,1898.36 5279.8,1898.36 v1(5359.51,1818.66)
  Bottom Layer w5.3: v1(5359.51,1818.66) 5420.14,1818.66 5466.48,1865 5750,1865 5843.5,1771.5 5843.5,1679.5 5855.48,1667.52 5855.48,1650.65 5921,1585.12 5921,1025.46 5865,969.46 5865,969.4 5609.36,969.4 5588.45,948.49 5570.38,948.49 5510,888.11 5510,702.53 5448.05,640.58 5448.05,469.67 5478.01,439.71 R335.1@5478.01,397.13
AM263_EQEP2_STROBE_R: R335.2 U43.9 | length 91.1
  Bottom Layer w5.3: R335.2@5478.01,349.89 5478.01,326.51 5495,309.52 U43.9@5538.7,309.52
AM263_EXT_REFCLK0: TP2.1 U1.P2 | length 637.5
  Top Layer w5.3: v1(3060,926.1) 3060,866.22 TP2.1@3061.79,864.43 ; v1(3298.62,925.4) 3311.89,938.67 3493.09,938.67 3510.79,956.37 3561.66,956.37 U1.P2@3578.63,973.35
  SIG 1 w5.3: v1(3060,926.1) 3065.9,932 3143.46,932 3172.83,961.37 3223.09,961.37 3234.52,949.94 3234.52,937.86 3246.99,925.4 v1(3298.62,925.4)
AM263_FSIRX1_CLK: J23.1 U1.E1 | length 2160.2
  Top Layer w4: 3515.64,1256.81 U1.E1@3547.13,1256.81
  Top Layer w5.3: J23.1@3404.17,1950 3331,1950 3213,1832 3213,1524 3147.98,1458.98 3147.98,1319.46 3170.54,1296.89 3255.82,1296.89 3285.71,1267 3439.5,1267 3449.69,1256.81 3515.64,1256.81
  Bottom Layer w5.3: v1(2975.61,1290) 2976.32,1290.71 2976.32,1418.09 3293.73,1735.5 3427.61,1735.5 3452.05,1759.94 3452.05,1902.13 J23.1@3404.17,1950
AM263_FSIRX1_DATA0: J23.5 U1.F3 | length 1782.6
  Top Layer w10: v1(3594.38,1241.06) U1.F3@3610.12,1225.32
  SIG 1 w4: 3515.64,1241.06 v1(3594.38,1241.06)
  SIG 1 w4.75: v1(2935,1290) 2953.56,1271.44 2966.94,1271.44 2967.63,1270.75 3038.25,1270.75 3052.5,1256.5 3125.39,1256.5 3140.82,1241.06 3515.64,1241.06
  Bottom Layer w5.3: v1(2935,1290) 2955,1270 2985,1270 3000,1285 3000,1426.78 3297.22,1724 3434,1724 3470,1760 3470,1825.78 3587.73,1943.5 3597.67,1943.5 J23.5@3604.17,1950
AM263_FSIRX1_DATA1: J23.7 U1.F4 | length 1770.2
  Top Layer w5.3: v1(3167.5,1347) 3167.5,1461.5 3223.6,1517.6 3223.6,1822 3307.1,1905.5 3659.67,1905.5 J23.7@3704.17,1950
  Top Layer w10: v1(3625.87,1241.06) U1.F4@3641.62,1225.32
  SIG 1 w4: 3515.64,1257.18 3609.75,1257.18 v1(3625.87,1241.06)
  SIG 1 w4.75: v1(3167.5,1347) 3156.21,1335.71 3081.21,1335.71 3071,1325.5 3071,1290 3081.5,1279.5 3141,1279.5 3163.32,1257.18 3515.64,1257.18
AM263_FSITX1_CLK: J23.2 R54.1 | length 1614.7
  Top Layer w5.3: R54.1@3190,1317.26 3190,1369 3180,1379 3180,1456.5 3239,1515.5 3239,1817.6 3314.9,1893.5 3708.49,1893.5 3747.18,1932.19 3747.18,2081.32 3717,2111.5 3465.67,2111.5 J23.2@3404.17,2050
AM263_FSITX1_CLK_R: R54.2 U1.E4 | length 479.6
  Top Layer w5.3: R54.2@3229.37,1317.26 3231.34,1317.26 3249,1334.92 v1(3249,1354.5)
  Top Layer w10: v1(3625.87,1272.56) U1.E4@3641.62,1256.81
  SIG 1 w4: 3516.64,1288.5 3609.93,1288.5 v1(3625.87,1272.56)
  SIG 1 w4.75: v1(3249,1354.5) 3288,1315.5 3458.5,1315.5 3485.5,1288.5 3516.64,1288.5
AM263_FSITX1_DATA0: J23.6 R57.1 | length 1115.8
  Top Layer w5.3: R57.1@3190,1274.26 3170.24,1274.26 3135.36,1309.14 3135.36,1461.35 3202.4,1528.39 3202.4,1838.9 3357,1993.5 3547.67,1993.5 J23.6@3604.17,2050
AM263_FSITX1_DATA0_R: R57.2 U1.F2 | length 369.5
  Top Layer w4: 3515.64,1242.05 3561.9,1242.05 U1.F2@3578.63,1225.32
  Top Layer w5.3: R57.2@3229.37,1274.26 3258.74,1274.26 3290.95,1242.05 3515.64,1242.05
AM263_FSITX1_DATA1: J23.8 R58.1 | length 1404.9
  Top Layer w5.3: R58.1@3190,1231.26 3145.39,1231.26 3118.16,1258.5 3104.44,1258.5 3075.16,1287.78 3075.16,1416.14 3190.7,1531.68 3190.7,1844.2 3353,2006.5 3532,2006.5 3553,2027.5 3553,2074 3573,2094 3660.17,2094 J23.8@3704.17,2050
AM263_FSITX1_DATA1_R: R58.2 U1.G2 | length 365.1
  Top Layer w4: 3515.64,1209.57 3562.88,1209.57 U1.G2@3578.63,1193.82
  Top Layer w5.3: R58.2@3229.37,1231.26 3231.74,1231.26 3249.78,1213.22 3499.19,1213.22 3502.3,1210.12 3502.3,1209.57 3515.64,1209.57
AM263_I2C1_SCL: J5/J7.49 R175.1 U1.D7 U16.6 U48.15 | length 9416.8
  Top Layer w5.3: U48.15@2052.72,1495 2084.14,1495 2093.57,1485.56 2093.57,1429.46 2135.7,1387.34 2271.11,1387.34 2338.06,1320.38 2421.5,1320.38 2465,1363.89 2465,1557.62 2540.58,1633.2 2540.58,1870.21 2594.07,1923.69 2594.07,1949.07 v1(2625,1980) ; J5/J7.49@4904.17,250 4904.17,160.51 R175.1@4903.31,159.65 4935.35,159.65 4970,125 4970,85 4988.58,66.42 5469.31,66.42 5517.89,115 5563.27,115 5655,206.73 v1(5655,421.38) 5616.38,460 5488.71,460 5460.6,488.11 5460.6,571.98 5477.76,589.14 U16.6@5545.51,589.14
  Top Layer w10: v1(3720.36,1304.06) U1.D7@3736.11,1288.31
  SIG 1 w4: v1(3720.36,1304.06) 3735.36,1319.06 3735.36,1414.29
  SIG 1 w4.75: 3735.36,1414.29 3735.36,1688.14 3764.25,1717.03 3764.25,1805.16 3769.25,1810.16 3769.25,1854.65 3875.05,1960.45 v1(3875.05,2090.05)
  Bottom Layer w5.3: v1(2625,1980) 2810.5,1980 2828,1997.5 2908,1997.5 2946,1959.5 3242.04,1959.5 3383.19,2100.65 3861.68,2100.65 3872.28,2090.05 v1(3875.05,2090.05) 3912.35,2090.05 3964.31,2038.09 4004.25,2038.09 4156.88,2190.72 5707.48,2190.72 5882.72,2015.49 5882.72,1854.22 5933.8,1803.13 6029.61,1803.13 6072.85,1759.89 6072.85,1659.68 6083.8,1648.73 6083.8,1316.2 6112.62,1287.38 6112.62,976.63 5984.47,848.48 5905.04,848.48 5827.42,926.1 5728.23,926.1 5682.27,880.14 5682.27,819.31 5749.4,752.17 5749.4,515.78 v1(5655,421.38)
AM263_I2C1_SDA: J5/J7.50 R176.1 U1.C8 U16.5 U48.2 | length 8634.5
  Top Layer w5.3: U48.2@2267.28,1495 2353.98,1495 2515,1656.02 2515,1875.92 2569.22,1930.14 2569.22,2003.42 v1(2605.48,2039.68) ; J5/J7.50@5004.17,250 R176.1@5004.17,159.65 5409.65,159.65 5515,265 5515,334.61 5570,389.61 v1(5570,420) 5545,445 5486.14,445 5450,481.14 5450,625 5464.14,639.14 U16.5@5545.51,639.14
  Top Layer w10: v1(3751.86,1335.55) U1.C8@3767.61,1319.8
  SIG 1 w4: v1(3751.86,1335.55) 3775.62,1359.32 3775.62,1425.57
  SIG 1 w4.75: 3775.62,1425.57 3775.62,1453.13 3753.75,1475 3753.75,1689.45 3774.3,1710 3774.3,1801 3779.3,1806 3779.3,1845.42 3930,1996.12 v1(3930,2024.75)
  Bottom Layer w5.3: v1(2605.48,2039.68) 2605.48,1969.13 2628.11,1946.5 3244.03,1946.5 3387.58,2090.05 3838.15,2090.05 3857.68,2070.53 3916.69,2070.53 3930,2057.21 v1(3930,2024.75) 4005.9,2024.75 4161.27,2180.12 5703.09,2180.12 5865,2018.21 5865,1854.37 5926.84,1792.53 5998.02,1792.53 6025,1765.56 6025,1672.52 6073.2,1624.32 6073.2,1311.78 6102.02,1282.96 6102.02,981.02 5980.08,859.08 5909.44,859.08 5830.92,937.6 5724.74,937.6 5665.6,878.46 5665.6,793.26 5738.8,720.06 5738.8,543.9 5614.9,420 v1(5570,420)
AM263_I2C3_SCL: J1/J3.9 R55.1 U1.H2 U35.2 | length 3534.8
  Top Layer w4: 3515.64,1177.69 3563.27,1177.69 U1.H2@3578.63,1162.32
  Top Layer w5.3: U35.2@1771.58,1462.4 1771.58,1392.87 1860,1304.45 1860,1226.21 1972.4,1113.81 1972.4,1015.62 1994.17,993.85 1995.98,993.85 1996.13,993.7 v1(2007.95,993.7) ; R55.1@2404.17,170 J1/J3.9@2404.17,250 ; v1(3180,1159.39) 3184.39,1155 3468.45,1155 3491.13,1177.69 3515.64,1177.69
  SIG 1 w4.75: v1(2007.95,993.7) 1967.11,1034.54 1967.11,1146.3 2060.3,1239.49 2233.05,1239.49 2263.97,1270.41 2864.95,1270.41 2896.36,1239 3002,1239 3059,1182 3126.24,1182 3148.86,1159.39 v1(3180,1159.39)
  Bottom Layer w5.3: v1(2007.95,993.7) 2055.85,945.8 2055.85,740.43 2070.48,725.81 2070.48,574.87 2089.88,555.47 2089.88,530.6 2184.8,435.67 2315.18,435.67 2360,390.85 2360,294.17 J1/J3.9@2404.17,250
AM263_I2C3_SDA: J1/J3.10 R56.1 U1.G3 U35.3 | length 3598.3
  Top Layer w5.3: U35.3@1797.17,1462.4 1797.17,1392.83 1840,1350 1980.45,1350 1999.67,1330.78 1999.67,1206.08 v1(1990,1196.41) ; R56.1@2504.17,170 J1/J3.10@2504.17,250
  Top Layer w10: v1(3594.38,1209.57) U1.G3@3610.12,1193.82
  SIG 1 w4.75: v1(1990,1196.41) 2043.74,1250.15 2227.14,1250.15 2257.45,1280.46 2879.35,1280.46 2909.85,1249.95 3015.1,1249.95 3034.05,1231 3104,1231 3124.42,1210.58 3593.37,1210.58 v1(3594.38,1209.57)
  Bottom Layer w5.3: v1(1990,1196.41) 2080.2,1196.41 2120.2,1156.41 2120.2,1031.38 2067.39,978.57 2067.39,743.89 2119.88,691.4 2119.88,618.02 2100.48,598.62 2100.48,535.88 2190.09,446.27 2393.73,446.27 2463.14,376.86 2463.14,291.04 J1/J3.10@2504.17,250
AM263_ICSSM_MII0_COL: R207.1 R219.2 R231.2 U37.45 U49.11 | length 2483
  Top Layer w5.3: v1(5835,786.84) U49.11@5877.2,786.84 ; R207.1@6674.39,1876.46 v1(6700,1876.46)
  SIG 1 w4.75: v1(5835,786.84) 5881.84,740 6304.59,740 6305.65,741.06 6350.52,741.06 6424.46,815 6531.49,815 6578.11,768.37 6578.11,738.69 6589.88,726.92 6710,726.92 6735.75,752.67 6735.75,981.83 6748.64,994.71 6748.64,1033.27 6713.34,1068.57 6713.34,1215.64 6765.6,1267.91 6765.6,1580.48 6748.64,1597.44 6748.64,1759.67 6700,1808.31 v1(6700,1876.46)
  Bottom Layer w5.3: U37.45@6674.39,1803.9 6674.52,1804.03 6674.52,1876.32 R219.2@6674.39,1876.46 v1(6700,1876.46) R231.2@6700,1985
AM263_ICSSM_MII0_CRS: U49.14
AM263_ICSSM_MII0_RXCLK: R196.1 U23.32 | length 2186.3
  Top Layer w5.3: U23.32@4892.17,1495.87 v1(5026.97,1495.87)
  SIG 1 w4.75: v1(5026.97,1495.87) 5052.52,1495.87 5130,1573.35 5130,1630 5148.88,1648.88 5190,1648.88 5205,1633.88 5205,1547.01 5218.7,1533.31 5272.43,1533.31 5290.93,1551.81 5290.93,1625.68 5314.12,1648.88 5351.12,1648.88 5368.7,1631.3 5368.7,1550.78 5381.13,1538.35 5447.26,1538.35 5458.38,1549.47 5458.38,1699.63 5542.5,1783.75 6128.06,1783.75 6213.36,1698.45 v1(6213.36,1620.91)
  Bottom Layer w5.3: v1(6213.36,1620.91) 6213.36,1644.73 6263.67,1695.04 R196.1@6351.89,1695.04
AM263_ICSSM_MII0_RXCLK_R: R196.2 U37.32 | length 94.1
  Bottom Layer w5.3: R196.2@6399.14,1695.04 6403.66,1699.57 U37.32@6491.32,1699.57
AM263_ICSSM_MII0_RXD0: R198.1 R203.1 R215.2 U23.41 | length 2259.9
  Top Layer w5.3: U23.41@4817.36,1629.73 4817.36,1674.62 4866.61,1723.86 v1(4893.56,1723.86) ; R203.1@6275,1752.65 6307.35,1752.65 v1(6315,1745)
  SIG 1 w4.75: v1(4893.56,1723.86) 4932.42,1685 5075.67,1685 5114.25,1723.58 5114.25,1750.62 5213.63,1850 5743.81,1850 5759.81,1834 5996.48,1834 6042.48,1880 6140,1880 6172.02,1912.02 6172.02,1976.07 6190.95,1995 6354.95,1995 6390,1959.95 6390,1773.91 6361.09,1745 v1(6315,1745)
  Bottom Layer w5.3: R215.2@6274.92,1752.65 6305.55,1752.65 6313.2,1745 v1(6315,1745) v1(6315,1745) R198.1@6351.89,1745.04
AM263_ICSSM_MII0_RXD0_R: R198.2 U37.33 | length 102.9
  Bottom Layer w5.3: R198.2@6399.14,1745.04 6434.21,1745.04 6460,1719.25 U37.33@6491.32,1719.25
AM263_ICSSM_MII0_RXD1: R199.1 R204.1 R216.2 U23.39 | length 2182.3
  Top Layer w5.3: U23.39@4856.73,1629.73 4856.73,1664.99 4861.74,1670 v1(4893.56,1670) ; v1(6274.92,1798.96) 6275,1799.04 R204.1@6275,1830.96
  SIG 1 w4.75: v1(4893.56,1670) 5074.88,1670 5195.38,1790.5 5386.09,1790.5 5419.54,1823.95 6004.95,1823.95 6049.09,1868.09 6142.3,1868.09 6182.07,1907.86 6182.07,1970.68 6196.35,1984.95 6350.79,1984.95 6379.95,1955.79 6379.95,1809.66 6345.29,1775 6298.88,1775 v1(6274.92,1798.96)
  Bottom Layer w5.3: v1(6274.92,1798.96) 6275,1799.04 R216.2@6275,1830.96 6275.11,1830.85 6335,1830.85 6351.89,1813.96 R199.1@6351.89,1795.04
AM263_ICSSM_MII0_RXD1_R: R199.2 U37.34 | length 126.8
  Bottom Layer w5.3: R199.2@6399.14,1795.04 6399.18,1795 6425.16,1795 6438.01,1782.15 6438.01,1762.74 6461.81,1738.94 U37.34@6491.32,1738.94
AM263_ICSSM_MII0_RXD2: R200.1 R210.1 R222.2 U23.38 | length 2143.2
  Top Layer w5.3: U23.38@4892.17,1613.98 4964.13,1613.98 v1(4983.82,1594.29) ; R210.1@6383.01,1989.35 6411.65,1989.35 v1(6411.73,1989.27)
  SIG 1 w4.75: v1(4983.82,1594.29) 5018.16,1594.29 5173.28,1749.41 5367.48,1749.41 5431.97,1813.9 6013.95,1813.9 6058.09,1858.04 6146.47,1858.04 6165.12,1876.69 6228.31,1876.69 6255.67,1849.33 6255.67,1760.83 6298.88,1717.62 6362.62,1717.62 6411.73,1766.73 v1(6411.73,1989.27)
  Bottom Layer w5.3: R200.1@6406.28,1918.62 6397.12,1927.78 6397.12,1950.5 6383.01,1964.61 R222.2@6383.01,1989.35 6411.65,1989.35 v1(6411.73,1989.27)
AM263_ICSSM_MII0_RXD2_R: R200.2 U37.35 | length 159.3
  Bottom Layer w5.3: R200.2@6406.28,1871.38 6406.28,1833.72 6448.61,1791.39 6448.61,1781.98 6471.97,1758.62 U37.35@6491.32,1758.62
AM263_ICSSM_MII0_RXD3: R201.1 R211.1 R223.2 U23.36 | length 2186
  Top Layer w5.3: U23.36@4892.17,1574.61 4964.13,1574.61 v1(4983.82,1554.92) ; R211.1@6443.01,1989.35 v1(6471.73,1989.27) v1(6471.73,1989.27)
  SIG 1 w4.75: v1(4983.82,1554.92) 4994.92,1554.92 5141.14,1701.14 5347.63,1701.14 5450.34,1803.85 6018.14,1803.85 6062.28,1847.99 6147.02,1847.99 6300.01,1695 6364.04,1695 6444.47,1775.43 6444.47,1999.47 6455,2010 6467.22,2010 6471.73,2005.49 v1(6471.73,1989.27)
  Bottom Layer w5.3: R201.1@6456.28,1918.62 6456.28,1943.72 6443.01,1956.99 R223.2@6443.01,1989.35 v1(6471.73,1989.27) v1(6471.73,1989.27)
AM263_ICSSM_MII0_RXD3_R: R201.2 U37.36 | length 116.2
  Bottom Layer w5.3: R201.2@6456.28,1871.38 6456.28,1798.71 6476.68,1778.31 U37.36@6491.32,1778.31
AM263_ICSSM_MII0_RXDV: R197.1 R205.1 R217.2 U23.34 | length 2223.6
  Top Layer w5.3: U23.34@4892.17,1535.24 4964.74,1535.24 v1(4984.43,1515.55) ; R205.1@6506.28,1989.43 6534.92,1989.43 v1(6535,1989.35)
  SIG 1 w4.75: v1(4984.43,1515.55) 5159.93,1691.06 5351.76,1691.06 5454.5,1793.8 6185.09,1793.8 6294.37,1684.51 6294.37,1663.83 6305.65,1652.56 6352.8,1652.56 6475.75,1775.51 6475.75,1890 6485.75,1900 6520,1900 6545,1925 6545,1979.35 v1(6535,1989.35)
  Bottom Layer w5.3: R197.1@6506.28,1918.62 R217.2@6506.28,1989.43 6534.92,1989.43 v1(6535,1989.35)
AM263_ICSSM_MII0_RXDV_R: R197.2 U37.38 | length 80
  Bottom Layer w5.3: R197.2@6506.28,1871.38 6506.28,1852.66 6536.59,1822.35 U37.38@6536.59,1803.9
AM263_ICSSM_MII0_RXER: R206.1 R218.2 R235.2 U37.46 U49.2 | length 2661.3
  Top Layer w5.3: v1(5574.59,914.8) 5600.18,889.2 U49.2@5652.8,889.2 ; v1(6694.07,1779.98) 6694.07,1810.03 6724.04,1840 6785,1840 6795,1850 6795,1874.79 R206.1@6796.28,1876.06 v1(6822.14,1876.06) R218.2@6848,1876.06
  SIG 1 w4.75: v1(5574.59,914.8) 5854.89,914.8 5986.39,783.3 6199.35,783.3 6216.09,800.03 6282.75,800.03 6307.03,775.75 6367.49,775.75 6416.79,825.05 6535.65,825.05 6593.6,767.1 6667.1,767.1 6719.25,819.25 6719.25,992.92 6703.29,1008.88 6703.29,1224.29 6755.55,1276.55 6755.55,1576.31 6735.75,1596.11 6735.75,1738.3 v1(6694.07,1779.98)
  Bottom Layer w5.3: v1(6694.07,1779.98) U37.46@6694.07,1803.9 ; v1(6822.14,1876.06) 6822.77,1876.69 R235.2@6848,1876.69
AM263_ICSSM_MII0_RXLINK: R208.1 R220.2 R233.2 U37.47 U49.5 | length 2777.1
  Top Layer w5.3: v1(5610.59,812.43) U49.5@5652.8,812.43 ; R208.1@6729.39,1876.46 v1(6758,1876.46)
  SIG 1 w4.75: v1(5610.59,812.43) 5689.53,812.43 5697.98,803.98 5737.42,803.98 5824.99,716.41 5881.68,716.41 5895.21,729.95 6278.26,729.95 6305.65,702.56 6329.24,702.56 6427.29,800.6 6531.62,800.6 6544.25,787.97 6544.25,768.34 6534.22,758.31 6534.22,738.69 6556.04,716.87 6741.87,716.87 6785,760 6785,975.92 6766.98,993.94 6766.98,1041.66 6723.39,1085.25 6723.39,1208.39 6775.65,1260.65 6775.65,1599.53 6765,1610.18 6765,1757.52 6730,1792.52 6730,1848.46 v1(6758,1876.46)
  Bottom Layer w5.3: U37.47@6713.76,1803.9 6713.76,1829.37 6729.39,1845 R220.2@6729.39,1876.46 v1(6758,1876.46) 6794.76,1876.46 R233.2@6795,1876.69
AM263_ICSSM_MII0_TXCLK: U23.19 U37.29 | length 2245
  Top Layer w5.3: v1(4797.68,1195.01) 4817.36,1214.69 U23.19@4817.36,1283.27
  SIG 1 w4.75: v1(4797.68,1195.01) 4816.93,1214.26 4816.93,1237.36 4835.53,1255.97 4858.36,1255.97 4865.13,1249.2 5026.48,1249.2 5100.59,1323.32 5271.68,1323.32 5295,1300 5497.08,1300 5574.45,1377.37 6203.73,1377.37 6221,1360.1 6329.33,1360.1 6364.23,1395 6412.71,1395 6516.08,1498.37 6516.08,1590.42 6483.53,1622.97 6461.5,1622.97 v1(6445,1606.47)
  Bottom Layer w5.3: v1(6445,1606.47) 6445,1619.87 6465.64,1640.51 U37.29@6491.32,1640.51
AM263_ICSSM_MII0_TXD0: U23.29 U37.28 | length 2238.6
  Top Layer w5.3: U23.29@4892.17,1436.81 v1(4933.82,1436.81)
  SIG 1 w4.75: v1(4933.82,1436.81) 4953.26,1456.25 5543.75,1456.25 5582.43,1417.57 6020,1417.57 6043.31,1440.89 6043.31,1533.31 6060,1550 6090.94,1550 6104.93,1536.01 6104.93,1437.02 6114.98,1426.97 6141.97,1426.97 6155,1440 6155,1575.32 6172.02,1592.34 6325.23,1592.34 6477.9,1745 6514.23,1745 6520,1739.23 v1(6520,1615)
  Bottom Layer w5.3: U37.28@6491.32,1620.83 6514.17,1620.83 v1(6520,1615)
AM263_ICSSM_MII0_TXD1: U23.27 U37.27 | length 2238.5
  Top Layer w5.3: U23.27@4892.17,1397.44 v1(4933.82,1397.44)
  SIG 1 w4.75: v1(4933.82,1397.44) 4982.58,1446.2 5073.64,1446.2 5097.17,1422.67 5116.6,1422.67 5125,1431.08 5125,1441.2 5130,1446.2 5145.03,1446.2 5150,1441.23 5150,1415.63 5157.93,1407.7 5171.95,1407.7 5180,1415.76 5180,1441.63 5184.57,1446.2 5200,1446.2 5204.29,1441.91 5204.29,1413.41 5210,1407.7 5225,1407.7 5231.71,1414.41 5231.71,1439.62 5237.09,1445 5250,1445 5255,1440 5255,1412.7 5260,1407.7 5280,1407.7 5286.71,1414.41 5286.71,1439.62 5292.09,1445 5305,1445 5310,1440 5310,1412.7 5315,1407.7 5330,1407.7 5336.71,1414.41 5336.71,1439.62 5342.09,1445 5355,1445 5360,1440 5360,1412.7 5365,1407.7 5380,1407.7 5386.71,1414.41 5386.71,1439.62 5392.09,1445 5405,1445 5410,1440 5410,1412.7 5415,1407.7 5430,1407.7 5436.71,1414.41 5436.71,1439.62 5442.09,1445 5455,1445 5460,1440 5460,1412.7 5465,1407.7 5480,1407.7 5486.71,1414.41 5486.71,1439.62 5492.09,1445 5505,1445 5510,1440 5510,1412.7 5515.18,1407.52 6145,1407.52 6175,1437.52 6175,1520.85 6206.45,1552.3 6404.57,1552.3 v1(6423.51,1571.24)
  Bottom Layer w5.3: v1(6423.51,1571.24) 6439.75,1571.24 6469.65,1601.14 U37.27@6491.32,1601.14
AM263_ICSSM_MII0_TXD2: U23.25 U37.26 | length 2245.1
  Top Layer w5.3: U23.25@4892.17,1358.07 v1(4933.82,1358.07)
  SIG 1 w4.75: v1(4933.82,1358.07) 4885,1358.07 4877.81,1365.27 4877.81,1413.87 4886.61,1422.67 4903.59,1422.67 4910,1416.26 4910,1391.44 4923.24,1378.19 4952.19,1378.19 4961,1387 4961,1401.85 4975.85,1416.69 4999.73,1416.69 5018.95,1397.47 5343.6,1397.47 5361.5,1379.57 5361.5,1351.08 5369.16,1343.42 5385.21,1343.42 5391.78,1349.99 5391.78,1389.25 5400,1397.47 5415,1397.47 5422.49,1389.98 5422.49,1350.49 5428.06,1344.92 5445.48,1344.92 5450,1349.43 5450,1390 5457.47,1397.47 5472.53,1397.47 5480,1390 5480,1348.38 5484.96,1343.42 5506.27,1343.42 5510,1347.15 5510,1392.47 5515,1397.47 6171.47,1397.47 6187.84,1413.84 6187.84,1517.25 6211.44,1540.85 v1(6444.47,1540.85)
  Bottom Layer w5.3: v1(6444.47,1540.85) 6444.47,1550.71 6475.21,1581.46 U37.26@6491.32,1581.46
AM263_ICSSM_MII0_TXD3: U23.23 U37.25 | length 2244.1
  Top Layer w5.3: U23.23@4892.17,1318.7 v1(4933.82,1318.7)
  SIG 1 w4.75: v1(4933.82,1318.7) 4999.46,1384.35 5314.02,1384.35 5369,1329.37 5512.23,1329.37 5570.29,1387.42 6195,1387.42 6213.36,1405.78 6213.36,1475.71 6227.65,1490 6254.55,1490 6265,1479.55 6265,1415.76 6275.11,1405.64 6300.52,1405.64 6307.97,1413.09 6307.97,1493.37 6320.6,1506 6336.86,1506 6351.36,1491.5 6351.36,1415.04 6360.4,1406 6383.17,1406 6397.17,1420 6397.17,1517.17 6401,1521 6430.92,1521 6434.76,1517.16 6434.76,1466.56 6442.03,1459.28 6452.69,1459.28 6492.17,1498.76 v1(6492.17,1540)
  Bottom Layer w5.3: U37.25@6491.32,1561.77 6491.32,1540.85 v1(6492.17,1540)
AM263_ICSSM_MII0_TXEN: U23.21 U37.37 | length 2239.7
  Top Layer w5.3: U23.21@4856.73,1283.27 4856.73,1230.38 v1(4857.11,1230)
  SIG 1 w4.75: v1(4857.11,1230) 5021.49,1230 5101.48,1309.99 5257.38,1309.99 5277.42,1289.95 5501.24,1289.95 5578.61,1367.32 6190.85,1367.32 6223.21,1334.96 6360.2,1334.96 6373.06,1347.82 6395.09,1347.82 6531.62,1484.35 6531.62,1572.37 6539.25,1580 6539.25,1622.97 6534.22,1628 6534.22,1764.68 v1(6495,1803.9)
  Bottom Layer w5.3: v1(6495,1803.9) U37.37@6516.91,1803.9
AM263_ICSSM_MII1_COL: R112.1 R124.2 R225.2 U1.C18 U22.45 | length 4456.8
  Top Layer w5.3: U1.C18@4082.57,1319.8 4086.6,1319.8 4122.5,1355.7 4170.68,1355.7 4201.68,1386.7 4363.56,1386.7 4387.19,1410.33 4387.19,1550.12 4367.66,1569.64 4367.66,1731.16 4416.75,1780.25 4796.75,1780.25 4840.66,1824.16 5119.95,1824.16 5194.97,1749.14 5412.42,1749.14 5618.28,1955 6545.79,1955 v1(6610,2019.21) ; R112.1@6674.39,926.46 v1(6700,926.46)
  SIG 1 w4.75: v1(6610,2019.21) 6655.14,1974.08 6655.14,1894.1 6684.3,1864.93 6684.3,1809.3 6674.82,1799.82 6674.82,1760.85 6716.13,1719.54 6716.13,1573.87 6710,1567.73 6710,1475.5 6745.5,1440 6745.5,1282.11 6674.39,1211 v1(6674.39,1065)
  Bottom Layer w5.3: U22.45@6674.39,853.9 6674.52,854.03 6674.52,926.32 R124.2@6674.39,926.46 v1(6700,926.46) 6700,1020 6715,1035 R225.2@6715,1064.94 6674.45,1064.94 v1(6674.39,1065)
AM263_ICSSM_MII1_RXCLK: U1.E16 U50.31 | length 1530.3
  Top Layer w5.3: v1(5131.16,1000.35) U50.31@5173.43,1000.35
  Top Layer w10: U1.E16@4019.57,1256.81 v1(4035.32,1272.56)
  SIG 1 w4: v1(4035.32,1272.56) 4051.82,1289.06 4114.06,1289.06
  SIG 1 w4.75: 4114.06,1289.06 4250.66,1289.06 4265.61,1304 4379.88,1304 4400.29,1324.4 4466.88,1324.4 4650,1141.28 4650,1127.38 4749.39,1027.99 4891.44,1027.99 4901.66,1038.21 5029.44,1038.21 5045,1022.66 5045,1007.89 5055.05,997.84 5080.12,997.84 5163.56,1081.29 5170.68,1081.29 5177.73,1074.24 5177.73,1041.58 5168.72,1032.57 5150.46,1032.57 5131.16,1013.27 v1(5131.16,1000.35)
AM263_ICSSM_MII1_RXD0: U1.F18 U50.42 | length 1527.9
  Top Layer w4: U1.F18@4082.57,1225.32 4113.77,1225.32 4114.06,1225.03
  Top Layer w5.3: 4114.06,1225.03 4115.16,1223.93 4182.78,1223.93 4232.43,1273.58 4368.23,1273.58 v1(4384.99,1256.82) ; v1(5248.23,759.55) 5267.91,779.23 U50.42@5267.91,846.81
  SIG 1 w4.75: v1(4384.99,1256.82) 4417.5,1256.82 4484.56,1189.75 4484.56,1133.75 4640.56,977.74 4847.67,977.74 4979.44,845.97 5058.54,845.97 5119.51,785 5222.77,785 v1(5248.23,759.55)
AM263_ICSSM_MII1_RXD1: U1.G16 U50.40 | length 1530
  Top Layer w5.3: v1(5208.86,759.55) 5208.86,785.31 5228.54,805 U50.40@5228.54,846.81
  Top Layer w10: U1.G16@4019.57,1193.82 v1(4035.32,1209.57)
  SIG 1 w4.75: v1(4035.32,1209.57) 4254.57,1209.57 4278.13,1233.13 4426.97,1233.13 4474.51,1185.59 4474.51,1129.58 4636.4,967.69 4843.5,967.69 4975.28,835.92 5054.38,835.92 5130.76,759.55 v1(5208.86,759.55)
AM263_ICSSM_MII1_RXD2: U1.E17 U50.37 | length 1526
  Top Layer w4: U1.E17@4051.07,1256.81 4066.82,1272.56 4101.95,1272.56 4113.62,1284.23 4114.06,1284.23
  Top Layer w5.3: 4114.06,1284.23 4158.05,1284.23 4210.42,1336.6 4250.64,1336.6 4281.86,1305.38 4367.8,1305.38 4377.05,1314.63 4436.95,1314.63 4460,1291.58 v1(4460,1271.09) ; v1(5131.77,882.24) U50.37@5173.43,882.24
  SIG 1 w4.75: v1(4460,1271.09) 4460,1264.54 4726.7,997.84 4860.42,997.84 4990.73,867.53 5070.26,867.53 5127.8,810 5158.56,810 5166.28,817.72 5166.28,868.95 5152.99,882.24 v1(5131.77,882.24)
AM263_ICSSM_MII1_RXD3: U1.E18 U50.35 | length 1529
  Top Layer w4: U1.E18@4082.57,1256.81 4104.96,1256.81
  Top Layer w5.3: 4104.96,1256.81 4121.72,1273.58 4171.45,1273.58 4192.65,1294.78 4372.19,1294.78 4372.51,1295.1 v1(4423.69,1295.1) ; v1(5131.77,921.61) U50.35@5173.43,921.61
  SIG 1 w4.75: v1(4423.69,1295.1) 4463.21,1295.1 4627.76,1130.55 4627.76,1113.02 4732.9,1007.89 4864.58,1007.89 4970.98,901.49 5157.7,901.49 5180,879.19 5180,853.61 5188.61,845 5208.86,845 5213.86,850 5213.86,875 5167.25,921.61 v1(5131.77,921.61)
AM263_ICSSM_MII1_RXDV: U1.F16 U50.33 | length 1526.7
  Top Layer w5.3: v1(5131.16,960.98) U50.33@5173.43,960.98
  Top Layer w10: U1.F16@4019.57,1225.32 v1(4035.32,1241.06)
  SIG 1 w4.75: v1(4035.32,1241.06) 4041.58,1234.81 4166.03,1234.81 4180,1248.78 4180,1259.38 4193.93,1273.3 4265,1273.3 4285.64,1293.95 4384.05,1293.95 4404.45,1314.35 4462.72,1314.35 4639.95,1137.12 4639.95,1115.05 4737.06,1017.94 4979.18,1017.94 5016.02,981.1 5142.47,981.1 5150.41,989.04 5150.41,1010.7 5159.71,1020 5173.32,1020 5177.73,1015.59 5177.73,969.09 5169.62,960.98 v1(5131.16,960.98)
